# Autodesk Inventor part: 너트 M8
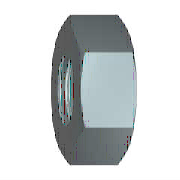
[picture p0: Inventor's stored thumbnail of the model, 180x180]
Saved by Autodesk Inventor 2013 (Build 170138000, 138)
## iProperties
IsCustomPart: 1
Created: 2012-02
Part Number: 너트 M8
Material: 강철, 연강
Description: 6각 너트 및 6각 가는 너트 - 이중 모따기
Document SubType Name: Modeling
Standard: KS B 1012
Designer: mduedu
Standards Organization: KS
Language: ko-KR
Size Designation: A M8
Categories: <MemberInstance><Categories><Category DisplayName="조임쇠" InternalName="e4da775c-781d-43d5-af7c-5136215cf5a6" Mnemonic="FSTN"><Category DisplayName="너트" InternalN
Density: 7.86 g/cm^3
Mass: 3.42669 g
Surface Area: 4.61759 cm^2
Volume: 0.435966 cm^3
Author: mduedu
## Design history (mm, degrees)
sketch "스케치1"
  geometry: L1 (-7.506, 0)-(-3.753, 6.5); L2 (-3.753, 6.5)-(3.753, 6.5); L3 (3.753, 6.5)-(7.506, 0); L4 (7.506, 0)-(3.753, -6.5); L5 (3.753, -6.5)-(-3.753, -6.5); L6 (-3.753, -6.5)-(-7.506, 0); 2 further points
  constraints: 12 end point, 1 coincident, 1 horizontal, 11 other
  dimensions: "d0" = 15.01111 distance of L3.end L1.start (= 1.1547 x SW)
extrude "본체" new body sketch "스케치1" distance "d1" = 4 (= KOH); taper "d2" = 0 deg
sketch "스케치2"
  geometry: L1 (0, 3.753)-(0, 7.506) reference; L2 (0, 7.506)-(4, 7.506) reference; L3 (4, 3.753)-(4, 7.506) reference; L4 (-0.8, 0)-(4.8, 0) reference; L5 (0.581, 7.506)-(0, 6.5); L6 (3.419, 7.506)-(4, 6.5)
  constraints: 4 end point, 4 point on line
  dimensions: "d3" = 30 deg angle of L1 L5 (= ANG1); "d4" = 30 deg angle of L3 L6 (= ANG2); "d5" = 13 diameter of L5.end L4 (= SW0); "d6" = 13 diameter of L6.end L4 (= SW01)
revolve "모따기1" sketch "스케치2" stored, may be unused: angle "d7" = 90 deg
sketch "스케치3"
  geometry: A1 r 6.5 centre (0, 0) between (-3.25, -5.629) and (3.25, -5.629) reference; 1 further point
  constraints: 1 coincident
hole "스레드" sketch "스케치3" at (0, 0) diameter "d25" = 6.647; stored, may be unused: countersink angle "d29" = 82 deg, drill point angle "d31" = 118 deg; dims "d26" = 6, "d27" = 4, "d28" = 2, "d30" = 8
workaxis "Work Axis1"
workplane "Work Plane1"
body "Solid1"
chamfer "모따기2" distance "d8" = 0.67658 (= -0.5 x GD1 + 0.5 x NND); stored, may be unused: angle "d9" = 30 deg, second distance "d40" = 0.67658 (= -0.5 x GD1 + 0.5 x NND)
chamfer "모따기3" distance "d10" = 0.67658 (= -0.5 x GD1 + 0.5 x NND); stored, may be unused: angle "d11" = 30 deg, second distance "d41" = 0.67658 (= -0.5 x GD1 + 0.5 x NND)
other parameters: "ANG1" = 30 deg [user parameter; used in 1 equation term], "ANG2" = 30 deg [user parameter; used in 1 equation term], "NND" = 8 [user parameter; used in 4 equation terms], "KOH" = 4 [user parameter; used in 1 equation term], "SW" = 13 [user parameter; used in 4 equation terms], "SW0" = 13 (= SW) [user parameter; used in 1 equation term], "SW01" = 13 (= SW) [user parameter; used in 1 equation term], "GD1" = 6.64684 (computed from THREADDIA, PTC, TOA) [user parameter; used in 4 equation terms], "d13" = 0, "d14" = 0, "d39" = 0, "d42" = 0, "GUL" = 0.67658 (= 0.541266 x PTC) [user parameter], "TPU" = 8 (computed from PTC) [user parameter], "THREADDIA" = 8 [user parameter; used in 1 equation term], "TOA" = 30 deg [user parameter; used in 1 equation term], "PTC" = 1.25 [user parameter; used in 4 equation terms], "E0" = 15.015 (= 1.155 x SW) [user parameter], "GAL" = 0.67658 (= 0.541266 x PTC) [user parameter]
